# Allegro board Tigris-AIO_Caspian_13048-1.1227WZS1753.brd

Outline 206.6 x 253.5 mm; copper layers: TOP, L2GND, L3, L4, L5GND, BOTTOM. Coordinates in mm from the lower left corner of the outline.
Outline path: 0,252.5 0,1 arc(0.29,0.29) 1,0 134,0 arc(134.58,0.18) 134.94,0.67 arc(135.13,0.91) 135.41,1 171,1 arc(171.71,1.29) 172,2 172,45.91 arc(172.01,46) 172.03,46.09 179.5,65.83 arc(179.68,66.06) 179.97,66.15 203.75,66.15 arc(204.46,66.44) 204.75,67.15 204.75,135.8 arc(205.04,136.51) 205.75,136.8 206.1,136.8 arc(206.45,136.95) 206.6,137.3 206.6,171.8 arc(206.45,172.15) 206.1,172.3 205.75,172.3 arc(205.04,172.59) 204.75,173.3 204.75,173.99 arc(204.67,174.37) 204.46,174.69 188.15,191 arc(188.04,191.17) 188,191.36 188,230 arc(187.71,230.71) 187,231 159.5,231 158,229.5 158,229.25 arc(157.85,228.9) 157.5,228.75 120.5,228.75 arc(120.15,228.9) 120,229.25 120,252.5 arc(119.71,253.21) 119,253.5 1,253.5 arc(0.29,253.21) 0,252.5

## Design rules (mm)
constraint set DEFAULT: min track width 0.127, pair gap 0.102
net group CARDREADER_20: nets CR_AUX_CAP CR_IO_CAP
net group GPU_ODT-MW: nets ODTA0 ODTA1
net group LED_10_6: nets PWR_LED_YELLOW_1 SUS_LED_GREEN_1
net group PWM_20_10: nets 1589_VCC AUD_REGREF
net group SIO_IT8731-4_5-MV-MW: nets SIO_ATXPG SIO_ATXPG_C
net group VRD_10_10-10.5: nets VCC_SENSE VSS_SENSE
net group 5MIL: nets 3.3V_RUN_VGA_1 5VDDCCL 5VDDCDA +19V_AMP_AVCC AUD_DVDD DDPB_CTRL_CLK DDPB_CTRL_DATA DDPC_CTRL_CLK DDPC_CTRL_DATA DDPD_CTRL_CLK DDPD_CTRL_DATA DISP_UTIL_CPU DPLL_PVDD DPLL_VDDC FDI_CSYNC FDI_INT G_H_DDCDA_1 G_H_DDCSCL_1 GND_AUD GPIO_8_ROMSO GPIO_9_ROMSI GPIO_10_ROMSCK GPIO_22_ROMCS# L_BKLTEN L_VDD_EN PCH_JTAG_PWR ROM_CS# ROM_SI_D3 ROM_SLK_D4 ROM_SO_C4 SA0_DIM0 SA0_DIM1 SA1_DIM0 SA1_DIM1 SATA1GP SATA3GP SIO_SPKR SPI_CLK SPI_CLK_1 SPI_CLK_R SPI_CS0_N SPI_CS0_N_R SPI_CS1_N SPI_IO2 SPI_IO2_R SPI_IO3 SPI_IO3_R SPI_MISO SPI_MISO_R SPI_MISO_ROM_1 SPI_MOSI SPI_MOSI_1 SPI_MOSI_R SPI_WP_N_1 SPKR SPKR_1 SPV10 SPV18 SST_HOLDJ_1 SWR_V12 TP_1P5_PCH_PWROK TP_1P5_PCH_PWROK_1 TP_ALL_PWRGD TP_CPU_G38 TP_CPU_H37 TP_CPU_H38 TP_CPU_J38 TP_CPU_K37 TP_CPU_K39 TP_CPU_M38 TP_CPU_N36 TP_CPU_T35 TP_DISP_J12 TP_DISP_K11 TP_GPIO52 TP_GPU_CLKREQ# TP_H_CATERR_N TP_LPC_DRQ0_N TP_NGFF_COEX1 TP_NGFF_COEX2 TP_NGFF_COEX3 TP_NGFF_LED1 TP_NGFF_LED2 TP_NGFF_MLDIR TP_PCH_A2 TP_PCH_A3 TP_PCH_AE30 TP_PCH_AH24 TP_PCH_AJ14 TP_PCH_AK14 TP_PCH_AM34 TP_PCH_AN16 TP_PCH_AP18 TP_PCH_AV13 TP_PCH_B1 TP_PCH_B2 TP_PCH_K16 TP_PCH_K22 TP_PCH_K33 TP_PCH_K34 TP_PCH_L16 TP_PCH_L22 TP_PCH_N12 TP_PCH_P19 TP_PCH_PWM0 TP_PCH_PWM1 TP_PCH_PWM2 TP_PCH_PWM3 TP_PCH_R12 TP_PCH_U10 TP_PCH_U11 TP_PEG_A4 TP_PEG_B3 TP_PEG_C2 TP_PEG_D1 TP_RSVD_AB6 TP_RSVD_AB33 TP_RSVD_AB36 TP_RSVD_AC8 TP_RSVD_AK20 TP_RSVD_AT40 TP_RSVD_AU1 TP_RSVD_AU27 TP_RSVD_AU39 TP_RSVD_AV1 TP_RSVD_AV2 TP_RSVD_AV20 TP_RSVD_AV24 TP_RSVD_AV29 TP_RSVD_AW2 TP_RSVD_AW12 TP_RSVD_AW23 TP_RSVD_AW24 TP_RSVD_AW27 TP_RSVD_AY18 TP_RSVD_C39 TP_RSVD_H12 TP_RSVD_H14 TP_RSVD_H15 TP_RSVD_H16 TP_RSVD_J8 TP_RSVD_J9 TP_RSVD_J10 TP_RSVD_J13 TP_RSVD_J15 TP_RSVD_J16 TP_RSVD_J17 TP_RSVD_J40 TP_RSVD_K8 TP_RSVD_K12 TP_RSVD_K13 TP_RSVD_L10 TP_RSVD_L12 TP_RSVD_M10 TP_RSVD_M11 TP_RSVD_N38 TP_RSVD_P33 TP_RSVD_P37 TP_RSVD_R33 TP_RSVD_R34 TP_RSVD_R36 TP_RSVD_T34 TP_RSVD_U8 TP_RSVD_V7 TP_RSVD_W8 TP_RSVD_Y8 TP_SLP_LAN_N_C TP_TPM_PIN6 TP_TPM_PIN7 V_1P5_DAC_FB V_1P5_DAC_FB_R V_1P05_DSW_INT_C V_1P05_DSW_INT_R V_1P05_ME V_1P05_PECI_VCOM V_1P5_RTC_INT V_1P05_XCK_DCB_FB_R V_3P3_BG V_5_CODEC V_CPU_VCCIO2PCH V_CPU_VCCIO_OUT V_CPU_VCCIO_RIGHT V_VCCIOA_LOAD VCCIO2PCH VCCST VGA_DDC_PU VGA_PCH_DDCSCL VGA_PCH_DDCSDA
net group 5MIL-1: nets H_PROCHOT_N H_PROCHOT_R_N H_VID0 H_VID1 H_VID2 H_VID3 H_VID4 H_VID5 H_VID6 H_VIDALERT_N H_VIDALERT_N_1 H_VIDALERT_N_VR H_VIDSCK H_VIDSCK_VR H_VIDSOUT H_VIDSOUT_VR PWR_VGA_CORE_VID0 PWR_VGA_CORE_VID1 PWR_VGA_CORE_VID2 PWR_VGA_CORE_VID3 PWR_VGA_CORE_VID4 PWR_VGA_CORE_VID5 PWR_VGA_CORE_VID6
net group 6MIL: nets DDRVTT_REF M_CAS_A_N M_MAA_A0 M_MAA_A1 M_MAA_A2 M_MAA_A3 M_MAA_A4 M_MAA_A5 M_MAA_A6 M_MAA_A7 M_MAA_A8 M_MAA_A9 M_MAA_A10 M_MAA_A11 M_MAA_A12 M_MAA_A13 M_MAA_A14 M_MAA_A15 M_RAS_A_N M_SBS_A0 M_SBS_A1 M_SBS_A2 M_WE_A_N TS#_DIMM0_1
net group 7.5MIL: nets M_ODT_A0 M_ODT_A1 M_SCKE_A0 M_SCKE_A1 M_SCS_A_N0 M_SCS_A_N1
net group 7MIL: nets DSWVRMEN FWH_ID0 INIT_3V L_AD0 L_AD0_R L_AD1 L_AD1_R L_AD2 L_AD2_R L_AD3 L_AD3_R L_FRAME_N L_FRAME_N_R L_PWRDWN_N LPC_DRQ1_N P_GNT_N1 P_GNT_N2 P_GNT_N3 P_INTA_N P_INTB_N P_INTC_N P_INTD_N P_PME# PCH_PCIECLKRQ1_N PCH_PCIECLKRQ5_N PCH_PCIECLKRQ6_N PCH_PCIECLKRQ6_N_1 PCH_RI SER_IRQ
net group 8.5MIL: nets M_DATA_A0 M_DATA_A1 M_DATA_A2 M_DATA_A3 M_DATA_A4 M_DATA_A5 M_DATA_A6 M_DATA_A7 M_DATA_A8 M_DATA_A9 M_DATA_A10 M_DATA_A11 M_DATA_A12 M_DATA_A13 M_DATA_A14 M_DATA_A15 M_DATA_A16 M_DATA_A17 M_DATA_A18 M_DATA_A19 M_DATA_A20 M_DATA_A21 M_DATA_A22 M_DATA_A23 M_DATA_A24 M_DATA_A25 M_DATA_A26 M_DATA_A27 M_DATA_A28 M_DATA_A29 M_DATA_A30 M_DATA_A31 M_DATA_A32 M_DATA_A33 M_DATA_A34 M_DATA_A35 M_DATA_A36 M_DATA_A37 M_DATA_A38 M_DATA_A39 M_DATA_A40 M_DATA_A41 M_DATA_A42 M_DATA_A43 M_DATA_A44 M_DATA_A45 M_DATA_A46 M_DATA_A47 M_DATA_A48 M_DATA_A49 M_DATA_A50 M_DATA_A51 M_DATA_A52 M_DATA_A53 M_DATA_A54 M_DATA_A55 M_DATA_A56 M_DATA_A57 M_DATA_A58 M_DATA_A59 M_DATA_A60 M_DATA_A61 M_DATA_A62 M_DATA_A63
net group 8MIL: nets SLP_SUSB SUS3V_FON_N SUS3V_ON_N SUS5V_ON_N SUS_PWR_ACK SUS_WARNB
net group 10MIL: nets BKLT_ADJ CLINK_CLK_LAN CLINK_CLK_LAN_1 CLINK_DATA_LAN CLINK_DATA_LAN_1 CLINK_RST_LAN_N CLINK_RST_LAN_N_1 CPU_FAN_CTRL_SIO CPU_FAN_TACH_SIO DPLVDS_EDIDCLK DPLVDS_EDIDCLK_C DPLVDS_EDIDSDA DPLVDS_EDIDSDA_C DPLVDS_FWCLK DPLVDS_FWCLK_C DPLVDS_FWSDA DPLVDS_FWSDA_C DPLVDS_ISPCLK DPLVDS_ISPDAT DPLVDS_PWMIN DPLVDS_PWMOUT EAPD_DEPOP FAN_CTL3 FAN_TAC3 GPIO_VGA_03_DATA GPIO_VGA_03_DATA_R GPIO_VGA_04_CLK GPIO_VGA_04_CLK_R H_PECI ISP_CLK1 ISP_DAT1 LVDS_BL_ADJ M1_SMB_CLK M1_SMB_DATA PCH_LVDS_BL_ADJ PECI_PCH PECI_READY PECI_SIO_R SIO_LVDS_BL_ADJ SIO_PECI_REQ_N SIO_SMBCLK1 SIO_SMBCLK2 SIO_SMBDAT1 SIO_SMBDAT2 SIO_TACH3 SMB_ALERT_N SMB_CLK_MAIN SMB_CLK_RESUME SMB_DATA_MAIN SMB_DATA_RESUME SMBUS_ISP SMLICLK_PCH SMLIDATA_PCH SMLINK0_CLK SMLINK0_DATA SP_CTS_N SP_DCD_N SP_DSR_N SP_DTR_N SP_RI_N SP_RTS_N SP_RXD_N SP_TXD_N SP_TXD_SIO SST_CTL_R SYS_FAN_TACH3_1 SYS_FAN_TACH3_2 SYSTEM_FAN_PWM1_2 TD_IREF
net group 12MIL: nets DDSP_B_TX_DN_3 DDSP_B_TX_DP_3 VGA_DACREFSET
net group 15MIL: nets A20GATE CK_14M_FLEX CK_14M_PCH CK_14M_SIO CK_14M_TPM CK_33M_PCI0 CK_33M_PCI1 CK_33M_PCI2 CK_33M_PCI3 CK_33M_PCI4 CK_P_33M_LPCP80 CK_P_33M_SIO CK_P_33M_TPM CK_PCH_33M_FB CLKOUTFLEX1 DMICOMP DMIRCOMP FDI_RCOMP HSYNC_3P3V NGFF_CLKREQ0_N NGFF_CLKREQ1_N PCIAUX_GATE PEG_COMP SATARBIAS_PCH SPKR_L+_SNB SPKR_L-_SNB SPKR_OUT_L+ SPKR_OUT_L- SPKR_OUT_R+ SPKR_OUT_R- SPKR_R+_SNB SPKR_R-_SNB SUS_PWR_ACK_R SUS_WARNB_R SUSCLK SUSCLK_1 SUSCLK_NGFF SUSCLK_SIO TPA3131_BSNL TPA3131_BSNR TPA3131_BSPL TPA3131_BSPR VGA_HSYNC_3V VGA_VSYNC_3V VSYNC_3P3V XCLK_RCOMP
net group 20MIL: nets BLUE_CRT GREEN_CRT LAN_XTALI LAN_XTALO PCH_RTCRST_DOWN PCH_RTCX1 PCH_RTCX2 RED_CRT RTCX_L VGA_BLUE VGA_BLUE_C_L VGA_GREEN VGA_GREEN_C_L VGA_RED VGA_RED_C_L XTAL_25M_PCH_IN XTAL_25M_PCH_OUT XTALIN XTALOUT
net group AUDIO-4MW: nets AUD_BEEP_C AUD_BEEP_R AUD_LINK_BCLK AUD_LINK_BCLK_R AUD_LINK_RST_N AUD_LINK_RST_R_N AUD_LINK_SDIN AUD_LINK_SDIN_1 AUD_LINK_SDO AUD_LINK_SDO_1 AUD_LINK_SDO_R AUD_LINK_SDO_R1 AUD_LINK_SYNC AUD_LINK_SYNC_R BUZZER_SPKR_R PCH_AUD_MUTE PCH_AUD_RST_N PCH_AUD_RST_N_1 TPA3113_SD1#
net group AUDIO-5: nets AUD_DMIC_CLK AUD_DMIC_CLK_R AUD_DMIC_DATA AUD_DMIC_DATA_R
net group AUDIO_AMP_15: nets AMP_SPKR_L AMP_SPKR_R PORTC_SPK_L PORTC_SPK_L_1 PORTC_SPK_R PORTC_SPK_R_1 SPKR_IN_L SPKR_IN_R TP3131_GVDD TPA3131_GAIN TPA3131_LINN TPA3131_LINN_1 TPA3131_MUTE TPA3131_PLIMIT TPA3131_RINN TPA3131_RINN_1 TPA3131_SYNC
net group AUDIO_DMIC_MW: nets AUD_DMIC_CLK_R_1
net group AUDIO_HDA-MW: nets AUD_LINK_RST_N_R AUD_LINK_SDO_N SENSE_B SLEEVE_G
net group AUDIO_IO: nets AUD_GP3 HPOL_CON HPOR_CON HPOUT-JD HPOUT-L HPOUT-R LINE2-VREFO LINEOUT-JD LINEOUT-L LINEOUT-R LINEOUT_C-L LINEOUT_C-R LINEOUT_CON-L LINEOUT_CON-R MIC2-L MIC2-L_1 MIC2-R MIC2-R_1 MIC2-VREFO-L MIC2-VREFO-R
net group AUDIO_IO_REF: nets JDREF MIC-CAP VRP
net group AUDIO_POP-MW: nets TPA3131_FAULT#
net group CARDREADER-4MW: nets CR_CLKREQ_N CR_LDOSEL CR_PE_REXT CR_WAKE0_N SD_CD# SD_CLK SD_CLK_C_1 SD_CLK_C_2 SD_CMD SD_CMD_C SD_DAT0 SD_DAT0_C SD_DAT1 SD_DAT1_C SD_DAT2 SD_DAT2_C SD_DAT3 SD_DAT3_C SD_LDO_EN SD_LED SD_WP
net group CPU-4MW: nets CPU_THERMTRIP_N H_PM_SYNC_0 H_PRDY_N H_PREQ_N H_SKTOCC_N H_SKTOCC_R_N H_TCK H_TDI H_TDO H_TMS H_TRST_N HSW_PCUDEBUG_0 HSW_PCUDEBUG_1 HSW_PCUDEBUG_2 HSW_PCUDEBUG_3 HSW_PCUDEBUG_4 HSW_PCUDEBUG_5 HSW_PCUDEBUG_6 HSW_PCUDEBUG_7 HSW_PCUDEBUG_8 HSW_PCUDEBUG_9 HSW_PCUDEBUG_10 HSW_PCUDEBUG_11 HSW_PCUDEBUG_12 HSW_PCUDEBUG_13 HSW_PCUDEBUG_14 HSW_PCUDEBUG_15 HSW_PCUSTB_0_DN HSW_PCUSTB_0_DP HSW_PCUSTB_1_DN HSW_PCUSTB_1_DP HSW_STRAP_13 HSW_XDP_MBP_0 HSW_XDP_MBP_1 PRIVACY_MSR_EN_N PWR_DEBUG PWR_DEBUG_1 PWR_DEBUG_N V_1P5_STBY_INT VCCST_PWRGD XDP_PWR_DEBUG
net group CPU-12: nets TPEV_CFG_RCOMP
net group DDR3_A-10: nets DIMM_CA_CPU_VREF_A DIMM_CA_CPU_VREF_RC DIMM_CA_VREF_A DIMM_CA_VREF_A_L DIMM_DQ_CPU_VREF_A DIMM_DQ_CPU_VREF_A_1 DIMM_DQ_CPU_VREF_B_1 DIMM_DQ_VREF_A DIMM_DQ_VREF_A_L
net group DDR3_B-5.5MW: nets M_DATA_B0 M_DATA_B1 M_DATA_B2 M_DATA_B3 M_DATA_B4 M_DATA_B5 M_DATA_B6 M_DATA_B7 M_DATA_B8 M_DATA_B9 M_DATA_B10 M_DATA_B11 M_DATA_B12 M_DATA_B13 M_DATA_B14 M_DATA_B15 M_DATA_B16 M_DATA_B17 M_DATA_B18 M_DATA_B19 M_DATA_B20 M_DATA_B21 M_DATA_B22 M_DATA_B23 M_DATA_B24 M_DATA_B25 M_DATA_B26 M_DATA_B27 M_DATA_B28 M_DATA_B29 M_DATA_B30 M_DATA_B31 M_DATA_B32 M_DATA_B33 M_DATA_B34 M_DATA_B35 M_DATA_B36 M_DATA_B37 M_DATA_B38 M_DATA_B39 M_DATA_B40 M_DATA_B41 M_DATA_B42 M_DATA_B43 M_DATA_B44 M_DATA_B45 M_DATA_B46 M_DATA_B47 M_DATA_B48 M_DATA_B49 M_DATA_B50 M_DATA_B51 M_DATA_B52 M_DATA_B53 M_DATA_B54 M_DATA_B55 M_DATA_B56 M_DATA_B57 M_DATA_B58 M_DATA_B59 M_DATA_B60 M_DATA_B61 M_DATA_B62 M_DATA_B63
net group DDR3_B-6.5MW: nets M_ODT_B0 M_ODT_B1 M_SCKE_B0 M_SCKE_B1 M_SCS_B_N0 M_SCS_B_N1
net group DDR3_B-8.5MW: nets M_CAS_B_N M_MAA_B0 M_MAA_B1 M_MAA_B2 M_MAA_B3 M_MAA_B4 M_MAA_B5 M_MAA_B6 M_MAA_B7 M_MAA_B8 M_MAA_B9 M_MAA_B10 M_MAA_B11 M_MAA_B12 M_MAA_B13 M_MAA_B14 M_MAA_B15 M_RAS_B_N M_SBS_B0 M_SBS_B1 M_SBS_B2 M_WE_B_N
net group DDR3_B-25: nets DIMM_CA_VREF_B DIMM_CA_VREF_B_L DIMM_DQ_CPU_VREF_B DIMM_DQ_VREF_B DIMM_DQ_VREF_B_L
net group DDR_COMP_12_25-12: nets DDR_RCOMP_0 DDR_RCOMP_1 DDR_RCOMP_2
net group DISPLAY-12: nets FDI_COMP
net group GND: nets VSS_MECH
net group GPIO_4-MW: nets ADAPTOR_PSID ADAPTOR_PSID_R DDSP_B_HPD DDSP_B_HPD_CONN JACK_PSID LVDS_DET_B_R NGFF_BT_DISABLE NGFF_DETECT_PCIE NGFF_DETECT_PCIE_C NGFF_DETECT_USB NGFF_DETECT_USB_C PCH_GP33_PU PCH_GPIO20 PSID_D PSID_D_1 PSID_G SIO_GREEN_GP000 SPKR_DET SPKR_DET_C USB_PWR_CRL1 USB_PWR_CRL1_B1 VGA_DET
net group GPIO_4-MW-4MW: nets 2136_HPD_C BIST_DISABLE BIST_EN_INV BIST_ENABLE BIST_ENABLE_1 BOARD_A BOARD_B BOARD_C DPD_HPD DPLVDS_HPD EAPD_DEPOP_1 GPIO17_THERMAL_INT GPIO19_CTF GPU_THERMAL_INT IGC_EN_N INTRUDER_DET INV_DET* IO_SMI_N LAN_DISABLE_N LPC_PME_N LVDS_DET_A* LVDS_DET_B* MB_SKU_ID0 MB_SKU_ID1 MB_SKU_ID2 ME_CNTL ME_CNTL1 ME_CNTL2 MPCIE_DISABLE_N OSD_BIST_N OSD_DN OSD_DN_R OSD_MENU OSD_MENU_R OSD_UP OSD_UP_R PANEL_SEL1_CABLE_PCH PANEL_SEL2_CABLE_PCH PANEL_SEL3_CABLE_PCH PCH_GP8 PCH_GP27_PU PECI_REQ_N PW_CLEAR PWRCN_DET_N QF2_1 QF2_2 SATA2GP SATA4GP SATA5GP SIO_HDD_LED SIO_HDD_LED_1 SLP_WLAN_N TMIN_SHIFT WEBCAM_DET
net group GPU-4MW: nets CLKTESTA CLKTESTA_C CLKTESTB CLKTESTB_C CTF_TRIP CTFB GPIO19_CTF_R GPU_THERM_SHUTDOWN* JTAG_TCK_VGA JTAG_TDI_VGA JTAG_TDO_VGA JTAG_TMS_VGA JTAG_TRST#_VGA MEM_CALRP0 MLPS_EN# PCIE_CALR_RX PCIE_CALR_TX PS_0 PS_1 PS_2 PS_3 VRAM_ZQ1 VRAM_ZQ2 VRAM_ZQ3 VRAM_ZQ4
net group GPU-20: nets MVREFDA MVREFSA VRAM1_VREFCA VRAM1_VREFDQ VRAM2_VREFCA VRAM2_VREFDQ VRAM3_VREFCA VRAM3_VREFDQ VRAM4_VREFCA VRAM4_VREFDQ
net group GPU_ADDRESS-MW: nets MAA0 MAA1 MAA2 MAA3 MAA4 MAA5 MAA6 MAA7 MAA8 MAA9 MAA10 MAA11 MAA12 MAA13 MAA_BA0 MAA_BA1 MAA_BA2
net group GPU_CTRL-MW: nets CASA0# CASA1# CKEA0 CKEA1 CSA0#_0 CSA1#_0 RASA0# RASA1# WEA0# WEA1#
net group GPU_DATA-MW: nets DQMA0 DQMA1 DQMA2 DQMA3 DQMA4 DQMA5 DQMA6 DQMA7 MDA0 MDA1 MDA2 MDA3 MDA4 MDA5 MDA6 MDA7 MDA8 MDA9 MDA10 MDA11 MDA12 MDA13 MDA14 MDA15 MDA16 MDA17 MDA18 MDA19 MDA20 MDA21 MDA22 MDA23 MDA24 MDA25 MDA26 MDA27 MDA28 MDA29 MDA30 MDA31 MDA32 MDA33 MDA34 MDA35 MDA36 MDA37 MDA38 MDA39 MDA40 MDA41 MDA42 MDA43 MDA44 MDA45 MDA46 MDA47 MDA48 MDA49 MDA50 MDA51 MDA52 MDA53 MDA54 MDA55 MDA56 MDA57 MDA58 MDA59 MDA60 MDA61 MDA62 MDA63
net group GPU_OTHER_4-6-MW: nets GPIO_SVC GPIO_SVD GPIO_SVT GPU_CLKA0_T GPU_CLKA1_T GPU_GPIO16 GPU_SCL GPU_SDA GPU_WAKEB GPU_XO_IN GPU_XO_IN2
net group GPU_VREF: nets GPU_VREFG
net group HDMI-MW: nets DDPC_CTRL_CLK_CONN DDPC_CTRL_DATA_CONN DDSP_C_HPD DDSP_C_HPD_CONN DDSP_D_TX_N0 DDSP_D_TX_N2 VCC5_DDC_HDMI
net group LAN_OTHER-4MW: nets LAN_RSET LANCLK_REQ_N LANCLK_REQ_U_N RTL_ISOLATE_N RTL_ISOLATE_N_1 RTL_ISOLATE_N_2
net group LAN_OTHER-10: nets LAN_P5_CN
net group LED_10_6-10: nets LAN_LEDACT_R# LINK_ACTIVITY_N PB_IN_SW1 PCH_SATA_LED_1 PCH_SATA_LED_N PCH_SATA_LED_R PWR_LED_YELLOW_C SIO_GREEN SIO_YELLOW SPEED_100*_CON SPEED_100_N SPEED_1000*_CON SPEED_1000_N SUS_LED_GREEN_C
net group NGFF_OTHER-MW: nets NGFF_ALERT_N NGFF_PEWAKE0_N NGFF_POWER_CTRL NGFF_POWER_CTRL_1 NGFF_W_DISABLE1_N NGFF_W_DISABLE2_N
net group OTHER_4_5-MW: nets CLKBUF_EN
net group OTHER_4_5-MW-4MW: nets CPU_VSS_T8 KCLK KDAT MCLK MDAT SYS_FAN_TACH1_1 SYS_FAN_TACH1_2 SYSTEM_FAN_PWM1_1 TESTLOW_1 TESTLOW_2 TP_DET
net group PANEL_CONTROL-MW: nets LVDS_PU_4 LVDS_PU_5 LVDS_PU_6 LVDS_PU_24 PANEL_ON_1 PANEL_ON_2 PANEL_ON_3 PANEL_ON_4 PANEL_ON_5 S_PANEL_ON
net group PANEL_CONTROL-MW-4MW: nets BKLT_EN BKLT_EN1 DPLVDS_BL_EN DPLVDS_PANEL_VCC PANEL_SEL1_CABLE PANEL_SEL2_CABLE PANEL_SEL3_CABLE S_LVDS_BL_EN
net group PCIE_PCIECLKRQ-MW: nets PCH_PCIECLKRQ5_N_1
net group POWER_RTC_35_5: nets VBAT1_C
net group POWER_RTC_35_5-35: nets V_3P0_BAT_VREG VBAT1_R VBAT2
net group POWER_SENSE_10_10: nets 12V_PWR_SENSE
net group PWM_10_10: nets 1589_COMP 1589_CP1 1589_FB 1589_FB1 1589_VOS RT8243_ENTRIP1_1 RT8243_ENTRIP1_2 RT8243_ENTRIP2_1 RT8243_ENTRIP2_2
net group PWM_10_10-10: nets 0D95V_VGA_FB 0D95V_VGA_FB_1 0D95V_VGA_FB_2 0D95V_VGA_FB_3 1D05V_EN 1D05V_RF 1D05V_TRIP 1D05V_VFB 1D8V_VGA_EN 1D8V_VGA_FB 1D8V_VGA_POK 1P5_PCH_EN 1P5_PCH_FB 3.3V_ALW_1 3D3V_VGA_S0_EN 62882_COMP_R 62882_FB_VSEN 62882_NTC_R 81102_COMP 81102_COMP_1 81102_COMP_2 81102_CSCCOMP 81102_CSCM_1 81102_CSREF 81102_CSSUM 81102_DIFF 81102_FB 81102_ILIM 81102_IOUT 81102_TSENSE 81102_TSENSE_R 81102_VSN 81102_VSP AUD_LINK_RST_N_2 BIST_DISABLE_1 BIST_EN BOOT1_PHASE1 D_RSMRST_N_1 D_RSMRST_N_2 DDR_EN DDR_PG DDR_RF DDR_TRIP DDR_VFB DRVON EAPD_DEPOP_2 GPUPG_1 GPUPG_2 GPUPG_3 H_PROCHOT_N_R LAN_DISABLE_N_1 LAN_DISABLE_N_2 LED_5VSB LED_V_5P0_A MB_REG_PG_1 MB_REG_PG_2 MB_REG_PG_3 MEM_REG_PG_1 MEM_REG_PG_2 OSD_BIST_N_1 PCH_1D05V_PG_R PHASE1_R PM_DPRSLPVR PRW_VGA_CORE_RBIAS PSI# PWM1_EN PWM2_EN PWM3_EN PWR2_PRSN_1 PWR2_PRSN_2 PWR_VGA_CORE_COMP PWR_VGA_CORE_DPRSLPVR PWR_VGA_CORE_IMON PWR_VGA_CORE_ISEN1 PWR_VGA_CORE_ISEN2 PWR_VGA_CORE_ISUM+ PWR_VGA_CORE_ISUM- PWR_VGA_CORE_NTC PWR_VGA_CORE_ON PWR_VGA_CORE_PGOOD PWR_VGA_CORE_PSI# PWR_VGA_CORE_RTN PWR_VGA_CORE_VSEN PWR_VGA_CORE_VSUM- PWR_VGA_CORE_VW RT8243_3D3VFB RT8243_5VFB RT8243_ENLDO RT8243_ENTRIP1 RT8243_ENTRIP2 RT8243_FB1 RT8243_FB2 RT8243_PGOOD RT8243_TON RT8243SECFB SP_TXD_N_1 SUS_ACK_EN_N SUS_PWR_ACK_5V_DUAL SUS_PWR_ACK_5V_DUAL_L SUS_PWR_ACK_BJT SUS_PWR_ACK_BJT_L TPA3113_SD TSVDD V5_ALW_MON V5_ALW_MON_1 V5_ALW_MON_2 VCC3_3SB_EN_2 VCC5SB_EN_2 VDDC_CT VR_TT# VREG_PCIAUX_PCH VREG_PCIAUX_PCH_1 VSUM_RC VSUM_RR
net group PWM_12_12: nets CSN2_R
net group PWM_12_12-12: nets CSN1 CSN2 CSN3 CSP1 CSP1_R CSP2 CSP2_R CSP3 CSP3_R PWM1 PWM2 PWM3 PWM4
net group PWM_20_10-20: nets 0D95V_VGA_SS 1D05V_V5IIN 81102_RAMP 81102_VCC APL5336_VCNTL CBN CBP CPVEE DDR_V5IIN DPLVDS_PIN16 FP_CBL_DET LDO_3D3V LDO_5V MB_REG_PG MEM_REG_PG PC_SPKR_DET PWM1_VCC PWM2_VCC PWM3_VCC PWR2_PRSNT PWR_VGA_CORE_BOOT1 PWR_VGA_CORE_FB PWR_VGA_CORE_FB2 PWR_VGA_CORE_VCCP PWR_VGA_CORE_VDD PWR_VGA_CORE_VIN PX_EN RT8243_LDO3 RT8243_LDO5 TESTEN TRST_N VIN_DET VREF_1
net group PWM_25_20: nets 1589_BOOT 1589_BT1 1589_LG 1589_LG12 1589_LX1_SNB 1589_UG 1589_UG1 AD+_2
net group PWM_25_20-25: nets 0D95V_VGA_DRV 0D95V_VGA_DRV_1 1D05V_DRVH 1D05V_DRVH_R 1D05V_DRVL 1D05V_SB 1D05V_VBST 1D05V_VBST_R 3D3VSB 5VSB DDR_DRVH DDR_DRVH_R DDR_DRVL DDR_SB DDR_VBST DDR_VBST_R PWM1_BT PWM1_BT_1 PWM1_HG PWM1_HG_1 PWM1_LG PWM1_SNB PWM2_BT PWM2_BT_1 PWM2_HG PWM2_HG_1 PWM2_LG PWM2_SNB PWM3_BT PWM3_BT_1 PWM3_HG PWM3_HG_1 PWM3_LG PWM3_SNB PWR_5V_BOOT1_1 PWR_VGA_CORE_LGATE1A PWR_VGA_CORE_LGATE1B PWR_VGA_CORE_SNB1 PWR_VGA_CORE_UGATE1 PWR_VGA_CORE_UGATE1_R RT8243_BOOT1 RT8243_BOOT2 RT8243_BOOT2_1 RT8243_HG1 RT8243_HG2 RT8243_LGATE1 RT8243_LGATE2 RT8243_UGATE1 RT8243_UGATE2
net group PWM_30_12-30: nets PCH_SATA_LED_2
net group PWM_PHASE: nets +VGA_CORE_PHASE1
net group PWR_EN_4_10-MW: nets 1589_PGOOD
net group PWR_EN_4_10-MW-4MW: nets PCH_1D05V_PG SLP_S3_N_R1 USB_EN USB_EN1 USB_EN2 V_VCC3P3_EN V_VCC3P3_EN_R V_VCC5_EN V_VCC5_EN_R VCTRL_VCC_EN
net group PWR_MONITER: nets INA99B_OUT INA991_IN_N INA991_IN_P LMV393IN+ LMV393IN-
net group PWRGD&RST_4-MW: nets 0D95V_VGA_EN ATX_ON* LAN_DISABLE_V3 NGFF_POWER_CTRL_V2 OCP_6 OCP_7 OCP_7_1 PLTRST_CR PLTRST_TPM_N PSPWRGD SIO_PSON_N_C SIO_PSON_N_C_1 SIO_PSON_N_C_2 SIO_PSON_N_C_3 SIO_PSON_N_C_4 SIO_PSON_N_C_5 SLP_S3_N_4 SLP_S4_N_G
net group PWRGD&RST_4-MW-4MW: nets 1P05_PCH_EN 1P05_PCH_EN_Q48 1P05_PCH_EN_Q48_R 1P05_PCH_EN_R 1P5_PCH_EN_R 1P5_PCH_EN_R_1 AMD_RST# DDR3_DRAMRST_N DDR3_DRAMRST_N_A_1 DDR3_DRAMRST_N_B_1 DDR_SHDN DGPU_PWROK DGPU_PWROK_1D5V DRAM_RST DRAM_RST_R FP_RST_PCH_N H_CPURST_N H_CPURST_SIO_N H_CPURST_SIO_N_1 H_DRAMPWRGD H_DRAMPWRGD_CPU H_PWRGD H_RSTOUT_XDP_N H_THERMTRIP_N KBRST_N LAN_DISABLE_N_3 LAN_DISABLE_N_4 MEM_COMP MEM_RST PCH_DPWROK PCH_MEPWROK_R PCH_RSMRST_N PCH_SLP_M_N PCH_SYSPWROK PCIE_RST# PCIRST1# PCIRST2# PLTRST*_SIO PLTRST_CPU_N PLTRST_CPU_N1 PLTRST_CPU_N2 PLTRST_LAN_N PLTRST_N PLTRST_N_R PLTRST_SL_N PWRBTN_N PWRGD_3V PWRGD_3V_B_1 PWRGD_3V_LL PWRGOOD_GPU PWROK3 PWROK3_1 Q46_PIN2 Q46_PIN3 Q46_PIN6 Q54_B Q54_C RSMRST*_R RSMRST_N RSMRST_SIO_N_1 SIO_PSON_N SLP_S3_N SLP_S3_N_1 SLP_S3_N_2 SLP_S3_N_3 SLP_S3_N_Q46 SLP_S4_N SLP_S4_N_R SLP_S4_SIO SLP_S5_N SUS_STAT_N V_SM_1P5_EN VR_READY WAKE_N XDP_DBRESET_N XDP_PLTRST_N XDP_PWRGD XDP_VR_READY
net group SIO_IT8731-4-4MW: nets SIO_PROCHOT_R_N
net group TCM_5: nets P25_GND TCM_BA0 TCM_BA1 TCM_CLK_RUN TCM_NC5# TCM_NCP
net group TP-MW: nets DCPSUS
net group USB-4MW: nets USB_OC1_R_N USB_OC2_R_N USBOC01* USBOC89* USBOC1011* USBRBIAS_PCH
net group VBAT_RST_4_10-MW-4MW: nets PCH_INTRUDER_L PCH_INTRUDER_N PCH_INTVRMEN PCH_RTCRST_PULLUP PCH_SRTCRSTB_PULLUP
net group XDP-MW-4MW: nets PCH_JTAG_RST_R PCH_JTAG_TCK PCH_JTAG_TDI PCH_JTAG_TDO PCH_JTAG_TMS

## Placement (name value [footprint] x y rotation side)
ATX1  PIN-CONN4B-GP  [G881A04102TEU]  11.06 166.05 270 top
ATX2  PIN-CONN8B-S-GP  [733-71-08TB12]  7.86 140.05 270 top
BT1  BAT-AAA-BAT-034-K01-GP  [AAA-BAT-034-K01]  82.62 215.35 180 top
BTPWR1  JOWLE-CON2-5-GP  [A2541WV0-1EX2PA-6T]  102.62 222.23 270 top
BTRST1  JOWLE-CON2-5-GP  [A2541WV0-1EX2PA-6T]  147.57 111.87 90 top
C1  SCD1U16V2KX-3GP  [C402H22]  104.27 242.55 90 top
C2  SCD1U16V2KX-3GP  [C402H22]  104.27 241.66 90 top
C3  SCD1U16V2KX-3GP  [C402H22]  102.87 240.78 90 top
C4  SCD1U16V2KX-3GP  [C402H22]  102.87 239.89 90 top
C5  SCD1U16V2KX-3GP  [C402H22]  104.65 238.87 90 top
C6  SCD1U16V2KX-3GP  [C402H22]  104.65 237.98 90 top
C7  SC1U10V2KX-1GP  [C402H22]  91 231.72 270 top
C8  SC2D2U10V3KX-1GP  [C603H36]  90.41 228.9 180 top
C9  SCD1U16V2KX-3GP  [C402H22]  91.57 228.52 180 top
C10  SC2K2P50V3KX-GP  [C603]  33.02 227.95 180 top
C11  SC10U25V6KX-4DL-GP  [C1206H71]  176.78 221.73 90 top
C12  SCD1U50V3KX-GP  [C603H36]  166.88 221.09 180 top
C13  SC10U25V6KX-4DL-GP  [C1206H71]  176.78 219.44 90 top
C14  SC10U6D3V3MX-GP  [C603H38]  123.83 217.53 0 top
C15  SC10U6D3V3MX-GP  [C603H38]  125.09 217.53 0 top
C16  SC10U25V6KX-4DL-GP  [C1206H71]  17.84 217.21 270 top
C17  SCD1U16V2KX-3GP  [C402H22]  122.81 217.15 0 top
C18  SC10U25V6KX-4DL-GP  [C1206H71]  176.78 217.15 90 top
C19  SC1U10V2KX-1GP  [C402H22]  143.23 216.37 180 top
C20  SCD1U16V2KX-3GP  [C402H22]  61.75 216.06 0 top
C21  SC1U10V2KX-1GP  [C402H22]  140.54 212.79 90 top
C22  SC10U10V5KX-2GP  [C805H54]  126.75 214.74 180 top
C23  SCD1U10V2KX-5GP  [C402H22]  128.4 214.61 180 top
C24  SCD1U10V2KX-5GP  [C402H22]  129.29 214.61 180 top
C25  SC100P50V2JN-3GP  [C402H22]  62.74 213.34 270 top
C26  SCD1U16V2KX-3GP  [C402H22]  72.52 209.15 270 top
C27  SC22U6D3V5MX-2GP  [C805H58]  129.49 211.95 90 top
C28  SC1U10V2KX-1GP  [C402H22]  143.76 211.82 180 top
C29  SCD1U10V2KX-5GP  [C402H22]  135.59 211.36 270 top
C30  SCD1U10V2KX-5GP  [C402H22]  128.78 210.52 90 top
C31  SC1U10V2KX-1GP  [C402H22]  145.8 208.77 0 top
C32  SC10U10V5KX-2GP  [C805H54]  124.23 208.49 180 top
C33  SCD1U10V2KX-5GP  [C402H22]  125.73 208.26 180 top
C34  SCD1U10V2KX-5GP  [C402H22]  130.18 208.01 180 top
C35  SCD1U10V2KX-5GP  [C402H22]  132.97 208.01 180 top
C36  SCD1U10V2KX-5GP  [C402H22]  131.57 207.5 270 top
C37  SC10U25V6KX-4DL-GP  [C1206H71]  17.91 207.25 90 top
C38  SCD1U16V2KX-3GP  [C402H22]  67.97 206.95 180 top
C39  SCD1U16V2KX-3GP  [C402H22]  79.12 206.1 90 top
C40  SCD1U16V2KX-3GP  [C402H22]  81.08 206.1 270 top
C41  SC1500P50V3KX-GP  [C603]  180.67 205.57 90 top
C42  SC2K2P50V3KX-GP  [C603]  33.4 205.09 0 top
C43  SC10U10V5KX-2GP  [C805H54]  131.19 204.71 270 top
C44  SC1U16V3KX-5GP  [C603H36]  161.93 198.23 90 top
C45  SC10U16V6KX-2GP  [C1206H71]  17.65 198 270 top
C46  SCD1U50V3KX-GP  [C603H36]  180.34 197.09 270 top
C48  SCD1U16V2KX-3GP  [C402H22]  175.77 194.93 270 top
C49  SCD1U16V2KX-3GP  [C402H22]  179.83 188.58 0 top
C50  SC1U16V3KX-2GP  [C603H36]  182.25 185.4 180 top
C51  SC10U16V6KX-2GP  [C1206H71]  17.91 179.82 270 top
C52  SC10U25V6KX-4DL-GP  [C1206H71]  17.91 177.61 270 top
C53  SC22U6D3V5MX-2GP  [C805H58]  76.58 175.31 90 top
C54  SC22U6D3V5MX-2GP  [C805H58]  80.18 175.31 90 top
C55  SC22U6D3V5MX-2GP  [C805H58]  83.76 175.31 270 top
C56  SC10U25V6KX-4DL-GP  [C1206H71]  17.91 175.4 270 top
C57  SC22U6D3V5MX-2GP  [C805H58]  76.58 173.28 90 top
C58  SC22U6D3V5MX-2GP  [C805H58]  80.18 173.28 90 top
C59  SC22U6D3V5MX-2GP  [C805H58]  83.76 173.28 270 top
C60  SC100P50V2JN-3GP  [C402H22]  44.99 171.81 90 top
C61  SC22U6D3V5MX-2GP  [C805H58]  76.58 171.25 90 top
C62  SC22U6D3V5MX-2GP  [C805H58]  80.18 171.25 90 top
C63  SC22U6D3V5MX-2GP  [C805H58]  83.76 171.25 270 top
C64  SC22U6D3V5MX-2GP  [C805H58]  76.58 169.22 90 top
C65  SC22U6D3V5MX-2GP  [C805H58]  80.18 169.22 90 top
C66  SC22U6D3V5MX-2GP  [C805H58]  83.76 169.22 270 top
C67  SCD1U25V3KX-GP  [C603H36]  25.4 167.88 0 top
C68  SC22U6D3V5MX-2GP  [C805H58]  76.58 167.19 90 top
C69  SC22U6D3V5MX-2GP  [C805H58]  80.18 167.19 90 top
C70  SC22U6D3V5MX-2GP  [C805H58]  83.76 167.19 270 top
C71  SC2K2P50V3KX-GP  [C603]  33.4 165.08 180 top
C72  SC22U6D3V5MX-2GP  [C805H58]  76.58 165.15 90 top
C73  SC22U6D3V5MX-2GP  [C805H58]  80.18 165.15 90 top
C74  SC22U6D3V5MX-2GP  [C805H58]  83.76 165.15 270 top
C75  SC1U16V3KX-5GP  [C603H36]  20.19 163.94 180 top
C76  SC22U6D3V5MX-2GP  [C805H58]  76.58 163.12 90 top
C77  SC22U6D3V5MX-2GP  [C805H58]  80.18 163.12 90 top
C78  SC22U6D3V5MX-2GP  [C805H58]  83.76 163.12 270 top
C79  SCD1U16V2KX-3GP  [C402H22]  144.91 162.8 180 top
C81  SC22U6D3V5MX-2GP  [C805H58]  76.58 161.09 90 top
C82  SC22U6D3V5MX-2GP  [C805H58]  80.18 161.09 90 top
C83  SC22U6D3V5MX-2GP  [C805H58]  83.76 161.09 270 top
C84  SCD1U50V3KX-GP  [C603H36]  19.05 148.95 90 bottom
C85  SCD1U25V3KX-GP  [C603H36]  28.45 133.08 0 top
C86  SCD1U25V3KX-GP  [C603H36]  27.18 133.08 0 top
C88  SCD1U16V2KX-3GP  [C402H22]  181.56 159.42 0 top
C89  SC22U6D3V5MX-2GP  [C805H58]  76.58 159.06 90 top
C90  SC22U6D3V5MX-2GP  [C805H58]  80.18 159.06 90 top
C91  SC22U6D3V5MX-2GP  [C805H58]  83.76 159.06 270 top
C92  SC4D7U6D3V3KX-GP  [C603H36]  180.43 158.8 180 top
C93  SCD1U16V2KX-3GP  [C402H22]  182.78 158.98 0 top
C94  SCD1U16V2KX-3GP  [C402H22]  179.2 158.53 0 top
C95  SC4D7U6D3V3KX-GP  [C603H36]  144.53 158.35 0 top
C97  SC4D7U6D3V3KX-GP  [C603H36]  178.29 156.97 270 top
C100  SCD1U16V2KX-3GP  [C402H22]  178.31 155.81 90 top
C101  SCD1U16V2KX-3GP  [C402H22]  180.09 154.29 90 top
C102  SC4D7U6D3V3KX-GP  [C603H36]  180.09 153.15 270 top
C103  SCD1U16V2KX-3GP  [C402H22]  144.27 153.02 0 top
C104  SCD1U16V2KX-3GP  [C402H22]  145.29 153.02 180 top
C105  SCD1U16V2KX-3GP  [C402H22]  183.13 151.88 0 top
C106  SC4D7U6D3V3KX-GP  [C603H36]  182.07 151.49 180 top
C108  SC4D7U6D3V3KX-GP  [C603H36]  179.83 150.73 270 top
C109  SC4D7U6D3V3KX-GP  [C603H36]  145.29 150.22 0 top
C110  SCD1U16V2KX-3GP  [C402H22]  175.23 148.09 180 top
C113  SCD1U25V3KX-GP  [C603H36]  29.44 154.59 270 top
C114  SC100P50V2JN-3GP  [C402H22]  142.49 137.7 90 top
C115  SCD1U16V2KX-3GP  [C402H22]  15.52 147.3 90 top
C116  SCD1U16V2KX-3GP  [C402H22]  15.47 145.91 90 top
C117  SC10U10V5KX-2GP  [C805H54]  185.67 131.94 0 top
C118  SCD1U16V2KX-3GP  [C402H22]  189.1 131.68 180 top
C119  SCD1U16V2KX-3GP  [C402H22]  179.2 124.95 180 top
C120  SCD1U16V2KX-3GP  [C402H22]  180.09 124.95 180 top
C121  SC10U25V5KX-GP  [C805H56]  14.99 125.84 90 top
C122  SCD1U25V3KX-GP  [C603H36]  14.61 124.19 270 top
C123  SCD1U16V2KX-3GP  [C402H22]  14.2 118.14 270 top
C124  SCD1U16V2KX-3GP  [C402H22]  14.22 116.95 270 top
C125  SCD1U16V2KX-3GP  [C402H22]  188.65 110.6 180 top
C126  SC10U10V5KX-2GP  [C805H54]  187.22 110.37 180 top
C127  SC1U10V2KX-1GP  [C402H22]  144.65 109.97 90 top
C128  SC1500P50V3KX-GP  [C603]  176.02 108.7 90 top
C129  SC1U25V3KX-1-GP  [C603H36]  12.32 106.28 180 top
C130  SC1U16V3KX-5GP  [C603H36]  159 105.77 0 top
C131  SC10U6D3V3MX-GP  [C603H38]  45.46 105.64 270 top
C132  SCD1U10V2KX-5GP  [C402H22]  45.59 104.49 270 top
C133  SCD22U10V2KX-1GP  [C402H22]  81.53 107.81 0 top
C134  SCD22U10V2KX-1GP  [C402H22]  82.42 107.81 0 top
C135  SCD22U10V2KX-1GP  [C402H22]  84.45 107.8 0 top
C136  SCD22U10V2KX-1GP  [C402H22]  85.34 107.8 0 top
C137  SCD22U10V2KX-1GP  [C402H22]  86.99 107.8 0 top
C138  SCD22U10V2KX-1GP  [C402H22]  87.88 107.8 0 top
C139  SCD22U10V2KX-1GP  [C402H22]  89.53 107.8 0 top
C140  SCD22U10V2KX-1GP  [C402H22]  90.42 107.8 0 top
C141  SCD1U50V3KX-GP  [C603H36]  165.33 103.54 180 top
C142  SCD1U10V2KX-5GP  [C402H22]  45.59 103.48 270 top
C143  SCD1U16V2KX-3GP  [C402H22]  183.92 103.34 270 top
C144  SCD1U16V2KX-3GP  [C402H22]  183.92 102.45 270 top
C145  SCD1U10V2KX-5GP  [C402H22]  44.19 101.95 180 top
C146  SCD22U10V2KX-1GP  [C402H22]  80.01 105.65 0 top
C147  SCD22U10V2KX-1GP  [C402H22]  80.9 105.65 0 top
C148  SCD22U10V2KX-1GP  [C402H22]  83.06 105.64 0 top
C149  SCD22U10V2KX-1GP  [C402H22]  83.94 105.64 0 top
C150  SCD22U10V2KX-1GP  [C402H22]  85.72 105.64 0 top
C151  SCD22U10V2KX-1GP  [C402H22]  86.61 105.64 0 top
C152  SCD22U10V2KX-1GP  [C402H22]  88.26 105.64 0 top
C153  SCD22U10V2KX-1GP  [C402H22]  89.15 105.64 0 top
C154  SCD1U16V2KX-3GP  [C402H22]  152.93 101.41 180 top
C155  SC10U25V6KX-4DL-GP  [C1206H71]  178.89 101.3 0 top
C156  SC10U25V6KX-4DL-GP  [C1206H71]  181.1 101.3 0 top
C157  SC1U16V3KX-5GP  [C603H36]  165.28 100.75 0 top
C158  SCD01U16V2KX-3GP  [C402H22]  44.45 99.93 180 top
C159  SCD1U50V3KX-GP  [C603H36]  182.83 100.42 0 top
C160  SC1U10V2KX-1GP  [C402H22]  129.67 99.55 90 top
C161  SC220P50V2KX-3DLGP  [C402H22]  176.66 96.68 180 top
C162  SC22P50V2JN-4GP  [C402H22]  183.13 96.38 0 top
C163  SCD1U10V2KX-5GP  [C402H22]  45.21 96.24 0 top
C164  SC10U6D3V3MX-GP  [C603H38]  180.85 96.12 90 top
C165  SC10U6D3V3MX-GP  [C603H38]  177.7 95.92 180 top
C166  SCD1U25V2KX-GP  [C402H22]  184.91 95.36 0 top
C167  SC100P50V2JN-3GP  [C402H22]  174.24 94.52 180 top
C168  SCD1U16V2KX-3GP  [C402H22]  180.47 94.98 90 top
C169  SC10U6D3V3MX-GP  [C603H38]  11.18 94.09 0 top
C170  SC100P50V2JN-3GP  [C402H22]  189.87 94.07 180 top
C172  SC1U10V2KX-1GP  [C402H22]  129.67 92.06 180 top
C173  SCD1U16V2KX-3GP  [C402H22]  133.99 91.98 180 top
C174  SC47P50V2JN-3GP  [C402H22]  117.06 92.02 180 top
C175  SC4D7U6D3V3KX-GP  [C603H36]  186.79 91.8 90 top
C176  SC4D7U6D3V3KX-GP  [C603H36]  189.43 90.41 90 top
C177  SC1U25V3KX-1-GP  [C603H36]  12.19 91.3 270 top
C178  SC1U10V2KX-1GP  [C402H22]  6.03 90.53 270 top
C179  SC2D2U10V3KX-1GP  [C603H36]  186.18 90.36 90 top
C180  SC10U10V5KX-2GP  [C805H54]  11.81 89.52 270 top
C182  SC10U10V5KX-2GP  [C805H54]  6.05 89.14 270 top
C183  SC1U10V2KX-1GP  [C402H22]  153.44 89.82 90 top
C184  SC10U10V5KX-2GP  [C805H54]  187.15 88.76 90 top
C185  SCD1U50V3KX-GP  [C603H36]  37.11 88.53 90 top
C186  SCD1U10V2KX-5GP  [C402H22]  45.72 87.6 270 top
C187  SCD1U16V2KX-3GP  [C402H22]  185.34 87.11 270 top
C188  SC1U10V2KX-1GP  [C402H22]  147.45 92.34 180 top
C189  SC1U10V2KX-1GP  [C402H22]  153.82 96.15 270 top
C190  SC10U25V6KX-4DL-GP  [C1206H71]  37.24 86.8 90 top
C191  SC15P50V3JN-GP  [C603H36]  154.2 86.78 0 top
C192  SCD1U10V2KX-5GP  [C402H22]  45.72 86.71 270 top
C193  SC10U10V5KX-2GP  [C805H54]  187.25 85.56 90 top
C194  SCD1U16V2KX-3GP  [C402H22]  184.56 85.63 0 top
C195  SC1U10V2KX-1GP  [C402H22]  172.26 85.76 270 top
C196  SC1U10V3KX-4GP-U  [C603H36]  173.96 84.59 270 top
C197  SC10U25V6KX-4DL-GP  [C1206H71]  37.24 84.59 90 top
C198  SCD1U16V2KX-3GP  [C402H22]  149.6 84.47 90 top
C199  SCD1U10V2KX-5GP  [C402H22]  44.99 84.14 180 top
C200  SCD68U16V3KX-GP-U  [C603H36]  95.89 88.5 90 top
C201  SC10U10V5KX-2GP  [C805H54]  185.8 82.53 0 top
C202  SC10U10V5KX-2GP  [C805H54]  187.96 82.53 0 top
C204  SC100P50V2JN-3GP  [C402H22]  180.59 81.9 0 top
C205  SC12P50V3JN-GP  [C603H36]  154.69 88.73 90 top
C206  SC100P50V2JN-3GP  [C402H22]  175.51 80.93 0 top
C207  SCD01U16V2KX-3GP  [C402H22]  43.56 80.75 270 top
C210  SC100P50V2JN-3GP  [C402H22]  179.07 80.12 90 top
C211  SCD1U10V2KX-5GP  [C402H22]  45.59 78.59 270 top
C212  SCD1U50V3KX-GP  [C603H36]  37.29 77.94 270 top
C213  SC10U25V6KX-4DL-GP  [C1206H71]  26.57 77.63 0 top
C214  SCD1U10V2KX-5GP  [C402H22]  45.59 77.7 270 top
C215  SC1U10V2KX-1GP  [C402H22]  150.75 75.17 90 top
C216  SCD1U10V2KX-5GP  [C402H22]  45.59 76.81 270 top
C218  SCD01U16V2KX-3GP  [C402H22]  16.41 73.59 180 top
C219  SC1U10V2KX-1GP  [C402H22]  193.68 74.3 0 top
C220  SCD01U16V2KX-3GP  [C402H22]  15.49 73.59 180 top
C222  SCD01U16V2KX-3GP  [C402H22]  14.55 71.42 180 top
C223  SC10U6D3V3MX-GP  [C603H38]  46.18 74.03 0 top
C224  SCD01U16V2KX-3GP  [C402H22]  13.67 71.42 180 top
C226  SCD1U16V2KX-3GP  [C402H22]  38.61 71.87 90 top
C227  SCD082U16V2KX-GP  [C402H22]  91.08 89.62 0 bottom
C228  SC1U10V3KX-3GP  [C603H36]  32.26 71.23 180 top
C229  SCD01U16V2KX-3GP  [C402H22]  38.61 70.98 90 top
C232  SCD1U16V2KX-3GP  [C402H22]  120.68 70.73 180 top
C236  SC1KP50V2KX-1GP  [C402H22]  33.91 68.69 90 top
C238  SCD22U16V3KX-2-GP  [C603H36]  34.29 67.55 90 top
C239  SCD1U25V2KX-GP  [C402H22]  55.17 67.46 270 top
C240  SC1U16V3KX-2GP  [C603H36]  151.76 31.23 0 top
C241  SCD1U16V2KX-3GP  [C402H22]  142.49 32.62 0 top
C242  SCD01U16V2KX-3GP  [C402H22]  36.58 66.4 270 top
C243  SCD1U16V2KX-3GP  [C402H22]  118.75 67.8 90 top
C244  SCD1U16V2KX-3GP  [C402H22]  118.75 66.91 90 top
C245  SC100P50V2JN-3GP  [C402H22]  75.69 64.88 0 top
C246  SC10U25V5KX-GP  [C805H56]  26.29 64.63 90 top
C247  SCD1U16V2KX-3GP  [C402H22]  120.65 64.63 270 top
C248  SCD1U16V2KX-3GP  [C402H22]  156.46 63.74 0 top
C249  SCD22U25V3KX-GP  [C603H40]  86.49 62.98 90 top
C250  SC1U10V2KX-1GP  [C402H22]  136.44 59.4 0 top
C251  SCD01U16V2KX-3GP  [C402H22]  16.89 58.4 270 top
C252  SCD01U16V2KX-3GP  [C402H22]  16.89 57.39 270 top
C253  SC2200P50V2KX-2GP  [C402H22]  55.98 56.3 270 top
C254  SCD01U16V2KX-3GP  [C402H22]  16.92 56.02 270 top
C255  SC2200P50V2KX-2GP  [C402H22]  57.4 55.41 270 top
C256  SCD01U16V2KX-3GP  [C402H22]  16.92 55.13 270 top
C257  SCD1U16V2KX-3GP  [C402H22]  133.99 54.69 270 top
C258  SC1U16V3KX-2GP  [C603H36]  149.45 54.8 90 top
C259  SC12P50V2JN-3GP  [C402H24]  117.34 53 270 top
C260  SC12P50V2JN-3GP  [C402H24]  119.38 53 90 top
C261  SC150P50V2JN-3GP  [C402H22]  128.11 52.18 90 top
C262  SC100P50V2JN-3GP  [C402H22]  42.09 52.16 90 top
C263  SCD1U25V3KX-GP  [C603H36]  149.22 46.72 90 top
C264  SC1U16V3KX-5GP  [C603H36]  139.57 50.49 90 top
C265  SC1U16V3KX-5GP  [C603H36]  128.46 48.66 0 top
C266  SC10U25V5KX-GP  [C805H56]  104.23 47.02 270 top
C267  0R3J-0-U-GP  [R603H22]  155.96 43.34 270 top
C268  SC1U16V3KX-2GP  [C603H36]  161.8 42.91 180 top
C269  SC1U16V3KX-2GP  [C603H36]  163.07 42.91 180 top
C270  SC10U16V6KX-2GP  [C1206H71]  131.96 46.81 270 top
C271  SC4D7U6D3V3KX-GP  [C603H36]  31.45 45.75 90 top
C272  SC1U10V2KX-1GP  [C402H22]  65.02 45.32 90 top
C273  SCD1U16V2KX-3GP  [C402H22]  31.14 44.66 90 top
C274  SCD027U50V3KX-DL-GP  [C603H36]  156.62 41.34 0 top
C275  SCD027U50V3KX-DL-GP  [C603H36]  159.13 40.75 0 top
C276  SCD1U16V2KX-3GP  [C402H22]  102.82 44.49 270 top
C277  SCD027U50V3KX-DL-GP  [C603H36]  165.23 40.5 270 top
C278  SC100P50V2JN-3GP  [C402H22]  158.12 41.13 0 top
C279  0R3J-0-U-GP  [R603H22]  167.26 41.26 0 top
C280  SC4D7U6D3V3KX-GP  [C603H36]  31.75 42.78 180 top
C281  SCD1U25V3KX-GP  [C603H36]  32.92 42.78 180 top
C282  SC470P50V3JN-2GP  [C603H36]  25.07 42.78 180 top
C283  SCD1U25V3KX-GP  [C603H36]  154.05 37.45 180 top
C284  SCD1U16V2KX-3GP  [C402H22]  25.86 41 270 top
C285  SCD1U16V2KX-3GP  [C402H22]  35.51 40.98 90 top
C286  SCD1U16V2KX-3GP  [C402H22]  35.51 40.09 90 top
C287  SCD027U50V3KX-DL-GP  [C603H36]  165.23 35.42 270 top
C288  SC12P50V2JN-3GP  [C402H24]  23.11 39.15 180 top
C289  SC1U10V2KX-1GP  [C402H22]  35.76 38.19 90 top
C290  SCD1U16V2KX-3GP  [C402H22]  16.76 37.07 270 top
C291  SCD1U16V2KX-3GP  [C402H22]  103.94 35.85 90 top
C292  SCD1U50V3KX-GP  [C603H36]  109.86 35.67 90 top
C293  SCD1U50V3KX-GP  [C603H36]  106.25 35.7 270 top
C294  SCD22U16V3KX-2-GP  [C603H36]  155.07 30.08 90 top
C295  SCD1U16V2KX-3GP  [C402H22]  35.77 35.1 90 top
C296  SCD22U16V3KX-2-GP  [C603H36]  164.72 30.97 0 top
C297  SCD1U16V2KX-3GP  [C402H22]  16.74 34.81 90 top
C298  SC10U10V5KX-2GP  [C805H54]  112.37 34.65 180 top
C299  SC12P50V2JN-DL-GP  [C402H22]  23.11 34.58 0 top
C300  SCD1U16V2KX-3GP  [C402H22]  35.77 34.18 90 top
C301  SCD22U16V3KX-2-GP  [C603H36]  157.99 30.08 270 top
C302  SCD22U16V3KX-2-GP  [C603H36]  160.91 30.08 90 top
C303  SCD1U16V2KX-3GP  [C402H22]  16.76 33.89 90 top
C304  SC1KP50V2KX-1GP  [C402H22]  116.51 33.31 270 top
C305  SC4D7U6D3V3KX-GP  [C603H36]  32.98 32.95 0 top
C306  SCD1U50V3KX-GP  [C603H36]  132.31 32.72 0 top
C307  SCD1U50V3KX-GP  [C603H36]  133.58 32.65 180 top
C308  SC4D7U6D3V2MX-GP-U  [C402-TO0D2H26]  63.5 32.62 0 top
C309  SC4D7U6D3V3KX-GP  [C603H36]  24.64 32.66 270 top
C310  SCD1U16V2KX-3GP  [C402H22]  44.7 29.83 180 top
C311  SCD1U16V2KX-3GP  [C402H22]  111 30.08 0 top
C312  SCD1U16V2KX-3GP  [C402H22]  16.76 30.11 270 top
C313  SCD01U50V3JX-1GP  [C603]  150.37 20.94 180 top
C314  SCD01U50V3JX-1GP  [C603]  152.53 26.78 90 top
C315  SCD01U50V3JX-1GP  [C603]  152.53 25.38 90 top
C316  SCD01U50V3JX-1GP  [C603]  149.61 30.59 90 top
C317  SC2D2U10V3KX-1GP  [C603H36]  32.13 29.32 90 top
C318  SCD1U10V2KX-4GP  [C402H20]  47.24 28.81 270 top
C319  SC470P50V3JN-2GP  [C603H36]  20.12 29.19 270 top
C320  SCD1U10V2KX-4GP  [C402H20]  35.43 28.56 270 top
C321  SC1KP50V2KX-1GP  [C402H22]  104.67 28.69 90 top
C322  SC470P50V2KX-3GP  [C402H22]  64.26 28.3 180 top
C323  SCD1U10V2KX-4GP  [C402H20]  47.24 27.92 270 top
C324  SCD1U10V2KX-4GP  [C402H20]  35.43 27.67 270 top
C325  SC1000P50V3JN-GP-U  [C603H36]  146.3 26.91 0 top
C326  SCD68U16V3KX-GP-U  [C603H36]  145.03 21.07 0 top
C327  SC1000P50V3JN-GP-U  [C603H36]  146.3 21.07 0 top
C328  SC1000P50V3JN-GP-U  [C603H36]  145.02 23.97 180 top
C329  SCD68U16V3KX-GP-U  [C603H36]  146.3 23.99 180 top
C330  SCD68U16V3KX-GP-U  [C603H36]  145.03 26.91 0 top
C331  SC1000P50V3JN-GP-U  [C603H36]  145.03 29.83 180 top
C332  SCD68U16V3KX-GP-U  [C603H36]  146.3 29.83 180 top
C333  SC10U10V5KX-2GP  [C805H54]  10.92 27.29 180 bottom
C334  SCD1U10V2KX-4GP  [C402H20]  47.93 26.63 270 top
C335  SCD1U10V2KX-4GP  [C402H20]  59.56 28.81 270 top
C336  SCD1U10V2KX-4GP  [C402H20]  35.43 26.4 270 top
C337  SCD1U10V2KX-4GP  [C402H20]  47.92 25.7 270 top
C338  SC470P50V3JN-2GP  [C603H36]  18.49 25.99 0 top
C339  SCD1U10V2KX-4GP  [C402H20]  35.43 25.51 270 top
C340  SCD1U50V3KX-GP  [C603H36]  131.72 25 0 top
C341  SCD1U50V3KX-GP  [C603H36]  132.97 24.98 0 top
C342  SC470P50V2KX-3GP  [C402H22]  60.07 27.42 180 top
C343  SC3D3P50V2CN-GP  [C402H22]  31.42 21.93 180 top
C344  SC3D3P50V2CN-GP  [C402H22]  40.08 21.88 180 top
C345  SC3D3P50V2CN-GP  [C402H22]  36.88 22.18 180 top
C346  SC3D3P50V2CN-GP  [C402H22]  33.5 21.93 180 top
C347  SC3D3P50V2CN-GP  [C402H22]  31.11 20.51 270 top
C348  SC3D3P50V2CN-GP  [C402H22]  37.36 18.6 90 top
C349  SC10P50V2JN-4GP  [C402H22]  33.15 19.41 90 top
C350  SC10P50V2JN-4GP  [C402H22]  39.32 19.59 90 top
C351  SC10P50V2JN-4GP  [C402H22]  35.23 19.44 270 top
C352  SC47P50V2JN-3GP  [C402H22]  34.54 14.87 180 top
C353  SC47P50V2JN-3GP  [C402H22]  34.49 16.85 180 top
C354  SCD1U16V2KX-3GP  [C402H22]  124.51 14.39 0 top
C355  SC100P50V2JN-3GP  [C402H22]  69.34 11.67 0 top
C356  SC100P50V2JN-3GP  [C402H22]  72.52 11.67 0 top
C357  SCD1U16V2KX-3GP  [C402H22]  113.21 10.07 0 top
C358  SC10U10V5KX-2GP  [C805H54]  111.68 9.94 180 top
C359  SCD1U16V2KX-3GP  [C402H22]  88.16 8.59 0 top
C360  SC10U10V5KX-2GP  [C805H54]  137.46 8.54 180 top
C361  SC10U10V5KX-2GP  [C805H54]  86.74 8.44 180 top
C362  SCD1U16V2KX-3GP  [C402H22]  98.45 7.43 180 top
C363  SC10U10V5KX-2GP  [C805H54]  99.9 7.38 180 top
C364  SCD1U16V2KX-3GP  [C402H22]  106.68 246.62 0 top
C365  SCD1U16V2KX-3GP  [C402H22]  20.32 245.96 0 bottom
C366  SCD1U16V2KX-3GP  [C402H22]  12.09 245.5 0 bottom
C367  SCD1U16V2KX-3GP  [C402H22]  54.86 245.22 0 bottom
C368  SCD1U16V2KX-3GP  [C402H22]  110.11 240.39 0 bottom
C369  SCD1U16V2KX-3GP  [C402H22]  23.67 244.48 0 bottom
C370  SCD01U50V2KX-1GP  [C402H22]  21.39 244.46 180 bottom
C371  SC47P50V2JN-3GP  [C402H22]  18.16 244.46 0 bottom
C372  SC2D2U16V5KX-1GP  [C805H58]  14.73 243.95 90 bottom
C373  SCD1U16V2KX-3GP  [C402H22]  111 240.39 0 bottom
C374  SCD1U16V2KX-3GP  [C402H22]  111.12 237.98 0 bottom
C375  SC1KP50V2KX-1GP  [C402H22]  11.58 242.58 90 bottom
C376  SCD1U16V2KX-3GP  [C402H22]  112.01 237.98 0 bottom
C377  SC4700P25V2KX-3-GP  [C402H24]  9.53 240.39 90 bottom
C378  SC470P50V2KX-3GP  [C402H22]  9.93 238.52 0 bottom
C379  SCD1U16V2KX-3GP  [C402H22]  22.89 238.01 270 bottom
C380  SC22P50V2JN-4GP  [C402H22]  11.94 237.6 180 bottom
C381  SCD1U16V2KX-3GP  [C402H22]  23.39 236.61 180 bottom
C382  SC2200P50V2KX-2GP  [C402H22]  9.4 235.82 90 bottom
C383  SC2200P50V2KX-2GP  [C402H22]  16.03 235.59 90 bottom
C384  SCD1U16V2KX-3GP  [C402H22]  24.64 235.57 180 bottom
C385  SCD01U25V2KX-3GP  [C402H22]  11.96 235.47 180 bottom
C386  SC100P50V2JN-3GP  [C402H22]  16 234.68 270 bottom
C387  SCD1U16V2KX-3GP  [C402H22]  21.87 234.07 90 bottom
C388  SCD1U16V2KX-3GP  [C402H22]  19.84 234.07 90 bottom
C389  SC1KP50V2KX-1GP  [C402H22]  24 232.77 270 bottom
C390  SC470P50V2KX-3GP  [C402H22]  10.92 232.39 180 bottom
C391  SC2D2U10V3KX-1GP  [C603H36]  106.3 228.71 0 bottom
C392  SCD1U16V2KX-3GP  [C402H22]  19.33 232.17 180 bottom
C393  SCD1U16V2KX-3GP  [C402H22]  21.34 232.14 180 bottom
C394  SCD1U16V2KX-3GP  [C402H22]  50.09 228.28 180 bottom
C395  SC1U16V3KX-5GP  [C603H36]  14.79 227.63 270 bottom
C396  SCD1U16V2KX-3GP  [C402H22]  174.75 227.06 270 bottom
C397  SC10U10V5KX-2GP  [C805H54]  174.88 225.66 270 bottom
C398  SC10U6D3V3MX-GP  [C603H38]  105.66 246.74 0 top
C399  SC10U6D3V3MX-GP  [C603H38]  105.03 228.71 0 bottom
C400  SCD1U25V3KX-GP  [C603H36]  22.65 224.9 0 bottom
C401  SCD1U16V2KX-3GP  [C402H22]  112.9 218.42 90 bottom
C402  SC4D7U10V5KX-4GP  [C805H56]  112.83 216.14 0 bottom
C403  SC1U16V3KX-5GP  [C603H36]  14.79 205.27 270 bottom
C404  SCD1U16V2KX-3GP  [C402H22]  133.35 203.44 0 bottom
C405  SCD1U16V2KX-3GP  [C402H22]  132.46 203.44 0 bottom
C406  SCD1U16V2KX-3GP  [C402H22]  128.65 201.3 270 bottom
C407  SCD1U16V2KX-3GP  [C402H22]  128.65 202.19 270 bottom
C408  SCD1U16V2KX-3GP  [C402H22]  127.64 204.07 270 bottom
C409  SCD1U16V2KX-3GP  [C402H22]  127.64 204.96 270 bottom
C410  SCD1U25V3KX-GP  [C603H36]  22.54 202.35 0 bottom
C411  SC4D7U6D3V3KX-GP  [C603H36]  65.66 201.79 0 bottom
C412  SCD1U10V2KX-5GP  [C402H22]  87.23 201.59 0 bottom
C413  SCD022U16V2KX-3GP  [C402H22]  84.05 201.58 0 bottom
C414  SCD1U16V2KX-3GP  [C402H22]  128.68 199.35 270 bottom
C415  SCD1U16V2KX-3GP  [C402H22]  128.68 198.46 270 bottom
C416  SC1U16V3KX-5GP  [C603H36]  184.28 194.42 0 bottom
C417  SCD022U16V2KX-3GP  [C402H22]  165.1 189.72 270 bottom
C418  SCD1U16V2KX-3GP  [C402H22]  157.48 188.32 180 bottom
C419  SCD1U16V2KX-3GP  [C402H22]  164.34 187.69 270 bottom
C420  SCD022U16V2KX-3GP  [C402H22]  159.51 187.31 180 bottom
C421  SC10U25V5KX-GP  [C805H56]  13.72 185.78 270 bottom
C422  SCD1U10V2KX-5GP  [C402H22]  173.48 181.21 270 bottom
C423  SCD1U10V2KX-5GP  [C402H22]  158.75 180.96 270 bottom
C424  SC22U6D3V5MX-2GP  [C805H58]  80.18 173.27 270 bottom
C425  SC22U6D3V5MX-2GP  [C805H58]  80.18 171.25 270 bottom
C426  SC22U6D3V5MX-2GP  [C805H58]  80.17 169.21 270 bottom
C427  SC22U6D3V5MX-2GP  [C805H58]  80.17 167.18 270 bottom
C428  SCD1U16V2KX-3GP  [C402H22]  174.24 164.58 270 bottom
C429  SC4D7U6D3V3KX-GP  [C603H36]  178.69 163.81 0 bottom
C430  SCD1U16V2KX-3GP  [C402H22]  163.83 163.81 180 bottom
C431  SCD1U16V2KX-3GP  [C402H22]  148.21 162.67 180 bottom
C432  SC1U10V2KX-1GP  [C402H22]  180.82 163.31 0 bottom
C433  SC4D7U6D3V3KX-GP  [C603H36]  157.63 162.01 180 bottom
C434  SCD1U16V2KX-3GP  [C402H22]  178.99 161.91 270 bottom
C435  SCD1U16V2KX-3GP  [C402H22]  173.74 161.91 90 bottom
C436  SCD1U16V2KX-3GP  [C402H22]  163.83 161.78 180 bottom
C437  SCD1U16V2KX-3GP  [C402H22]  178.99 160.89 270 bottom
C438  SC1U10V2KX-1GP  [C402H22]  186.18 160.77 270 bottom
C439  SC4D7U6D3V3KX-GP  [C603H36]  173.35 160.77 270 bottom
C440  SC4D7U6D3V3KX-GP  [C603H36]  81.31 160.18 0 bottom
C441  SC4D7U6D3V3KX-GP  [C603H36]  186.58 159.69 90 bottom
C442  SCD1U16V2KX-3GP  [C402H22]  157.61 159.5 0 bottom
C443  SC4D7U6D3V3KX-GP  [C603H36]  163.83 159.37 0 bottom
C444  SCD1U16V2KX-3GP  [C402H22]  174.12 158.73 90 bottom
C445  SCD1U16V2KX-3GP  [C402H22]  186.94 158.61 270 bottom
C446  SCD1U16V2KX-3GP  [C402H22]  186.94 157.72 270 bottom
C447  SCD1U16V2KX-3GP  [C402H22]  174.12 157.72 90 bottom
C448  SCD1U16V2KX-3GP  [C402H22]  163.58 156.45 180 bottom
C449  SC4D7U6D3V3KX-GP  [C603H36]  147.96 156.32 180 bottom
C450  SCD1U16V2KX-3GP  [C402H22]  157.61 156.19 180 bottom
C451  SC1U25V3KX-1-GP  [C603H36]  17.78 145.37 90 bottom
C452  SCD1U16V2KX-3GP  [C402H22]  72.77 155.25 270 bottom
C453  SCD1U16V2KX-3GP  [C402H22]  163.58 154.42 0 bottom
C454  SC4D7U6D3V3KX-GP  [C603H36]  157.61 153.78 0 bottom
C455  SC4D7U6D3V3KX-GP  [C603H36]  147.96 152.89 180 bottom
C456  SCD1U16V2KX-3GP  [C402H22]  178.44 152.51 90 bottom
C457  SCD1U16V2KX-3GP  [C402H22]  163.58 152.38 0 bottom
C458  SCD1U16V2KX-3GP  [C402H22]  178.44 151.49 90 bottom
C459  SC4D7U6D3V3KX-GP  [C603H36]  174.37 151.11 270 bottom
C460  SC4D7U6D3V3KX-GP  [C603H36]  178.82 150.35 90 bottom
C461  SC5P50V2CN-2GP  [C402H22]  183.13 150.22 90 bottom
C462  SCD01U50V2KX-1GP  [C402H22]  16 131.17 180 bottom
C463  SC4D7U6D3V3KX-GP  [C603H36]  174.37 149.84 270 bottom
C464  SC4D7U6D3V3KX-GP  [C603H36]  158.01 149.06 180 bottom
C465  SC4D7U6D3V3KX-GP  [C603H36]  147.96 148.95 0 bottom
C466  SCD1U50V3KX-GP  [C603H36]  17.02 130.92 180 bottom
C467  SCD1U16V2KX-3GP  [C402H22]  156.97 148.7 180 bottom
C468  SCD1U16V2KX-3GP  [C402H22]  157.61 147.18 90 bottom
C469  SCD1U16V2KX-3GP  [C402H22]  163.8 126.48 90 bottom
C470  SCD1U16V2KX-3GP  [C402H22]  163.8 125.59 90 bottom
C471  SCD1U16V2KX-3GP  [C402H22]  149 125.36 270 bottom
C472  SCD1U16V2KX-3GP  [C402H22]  152.17 125.23 270 bottom
C473  SC4D7U6D3V3KX-GP  [C603H36]  172.09 125.08 0 bottom
C474  SCD1U16V2KX-3GP  [C402H22]  152.15 124.27 270 bottom
C475  SC4D7U6D3V3KX-GP  [C603H36]  157.12 124.09 270 bottom
C476  SCD1U16V2KX-3GP  [C402H22]  163.83 123.55 90 bottom
C477  SC1U16V3KX-5GP  [C603H36]  135.89 118.47 270 bottom
C478  SC10U16V6KX-2GP  [C1206H71]  135.59 116.67 270 bottom
C479  SC10U25V5KX-GP  [C805H56]  16.89 117.71 0 bottom
C480  SC1KP50V2KX-1GP  [C402H22]  184.99 115.5 180 bottom
C481  SCD1U16V2KX-3GP  [C402H22]  136.42 112.46 270 bottom
C482  SC1U16V3KX-5GP  [C603H36]  129.16 108.82 270 bottom
C483  SC10U16V6KX-2GP  [C1206H71]  136.25 108.24 180 bottom
C484  SC1U16V3KX-5GP  [C603H36]  138.02 108.11 180 bottom
C486  SCD1U10V2KX-5GP  [C402H22]  45.59 105.13 90 bottom
C488  SC10U10V5KX-2GP  [C805H54]  143.12 104.16 90 bottom
C489  SCD1U10V2KX-5GP  [C402H22]  45.59 104.11 90 bottom
C500  SCD1U10V2KX-5GP  [C402H22]  45.59 102.35 90 bottom
C501  SCD1U16V2KX-3GP  [C402H22]  147.52 101.75 180 bottom
C502  SCD1U16V2KX-3GP  [C402H22]  146.63 101.75 180 bottom
C503  SC1U10V2KX-1GP  [C402H22]  145.74 101.75 180 bottom
C504  SC1U10V2KX-1GP  [C402H22]  144.85 101.75 180 bottom
C505  SC1U10V2KX-1GP  [C402H22]  143.96 101.75 180 bottom
C514  SCD1U10V2KX-5GP  [C402H22]  45.59 101.33 90 bottom
C515  SC10U10V5KX-2GP  [C805H54]  152.92 100.83 180 bottom
C516  SCD1U10V2KX-5GP  [C402H22]  45.59 100.3 90 bottom
C525  SC10U10V5KX-2GP  [C805H54]  186.94 84.18 0 bottom
C529  SCD1U10V2KX-5GP  [C402H22]  44.19 96.24 180 bottom
C533  SC100P50V2JN-3GP  [C402H22]  183.18 95.51 0 bottom
C539  SCD1U16V2KX-3GP  [C402H22]  147.7 93.84 180 bottom
C540  SCD1U10V2KX-5GP  [C402H22]  45.84 93.7 90 bottom
C544  SCD1U16V2KX-3GP  [C402H22]  175.9 87.23 0 bottom
C545  SC100P50V2JN-3GP  [C402H22]  150.86 91.92 0 bottom
C548  SCD1U50V3KX-GP  [C603H36]  134.47 91.55 0 bottom
C550  SCD1U16V2KX-3GP  [C402H22]  176.96 91.6 90 bottom
C551  SC100P50V2JN-3GP  [C402H22]  145.54 91.3 0 bottom
C552  SC100P50V2JN-3GP  [C402H22]  144.65 91.3 0 bottom
C554  SCD1U10V2KX-5GP  [C402H22]  58.67 90.66 90 bottom
C557  SCD1U10V2KX-5GP  [C402H22]  45.85 93.71 270 top
C558  SCD1U10V2KX-5GP  [C402H22]  90.6 85.02 180 bottom
C559  SCD1U10V2KX-5GP  [C402H22]  62.23 91.67 270 bottom
C560  SC10U6D3V3MX-GP  [C603H38]  177.32 90.56 90 bottom
C562  SC10U6D3V3MX-GP  [C603H38]  177.8 85.68 270 bottom
C565  SCD68U16V3KX-GP-U  [C603H36]  98.17 90.92 0 top
C570  SC10U6D3V3MX-GP  [C603H38]  175.01 84.69 90 bottom
C572  SCD1U16V2KX-3GP  [C402H22]  176.78 87.23 180 bottom
C578  SC100P50V2JN-3GP  [C402H22]  148.08 86.04 180 bottom
C579  SC1U10V2KX-1GP  [C402H22]  125.48 85.58 0 bottom
C581  SCD1U16V2KX-3GP  [C402H22]  146.22 85.49 90 bottom
C583  SCD1U10V2KX-5GP  [C402H22]  59.22 84.96 0 bottom
C584  SCD1U16V2KX-3GP  [C402H22]  172.85 81.14 90 bottom
C588  SCD1U10V2KX-5GP  [C402H22]  44.96 84.17 0 bottom
C591  SC1U10V2KX-1GP  [C402H22]  147.96 84.06 270 bottom
C593  SCD082U16V2KX-GP  [C402H22]  91.08 91.53 180 bottom
C598  SCD1U16V2KX-3GP  [C402H22]  126.11 82.66 180 bottom
C599  SCD1U16V2KX-3GP  [C402H22]  127.07 82.64 180 bottom
C600  SCD1U16V2KX-3GP  [C402H22]  151.76 82.03 270 bottom
C601  SC1500P50V3KX-GP  [C603]  29.87 81.95 180 bottom
C602  SCD1U10V2KX-5GP  [C402H22]  45.59 81.76 90 bottom
C606  SCD1U16V2KX-3GP  [C402H22]  149.83 80.13 90 bottom
C608  SCD1U10V2KX-5GP  [C402H22]  43.94 79.09 180 bottom
C609  SC10U6D3V3MX-GP  [C603H38]  136.14 78.63 270 bottom
C612  SCD1U10V2KX-5GP  [C402H22]  45.59 77.57 90 bottom
C613  SC1U10V2KX-1GP  [C402H22]  133.35 77.49 90 bottom
C616  SCD1U10V2KX-5GP  [C402H22]  45.59 76.55 90 bottom
C619  SC1U10V2KX-1GP  [C402H22]  135.53 76.26 180 bottom
C623  SCD1U10V2KX-5GP  [C402H22]  45.59 75.93 270 top
C625  SC1U10V2KX-1GP  [C402H22]  133.55 75.15 270 bottom
C627  SCD1U10V2KX-5GP  [C402H22]  45.59 74.52 90 bottom
C628  SC1U10V2KX-1GP  [C402H22]  136.09 74.29 90 bottom
C631  SC1U10V2KX-1GP  [C402H22]  138.3 73.81 180 bottom
C632  SC1U10V2KX-1GP  [C402H22]  134.03 73.73 180 bottom
C633  SCD1U16V2KX-3GP  [C402H22]  139.87 72.93 180 bottom
C634  SCD1U16V2KX-3GP  [C402H22]  115.06 227.44 180 bottom
C635  SCD1U16V2KX-3GP  [C402H22]  115.95 227.44 180 bottom
C636  SC1U10V2KX-1GP  [C402H22]  136.9 72.71 90 bottom
C638  SC1U10V2KX-1GP  [C402H22]  138.3 71.88 180 bottom
C639  SCD1U16V2KX-3GP  [C402H22]  134.03 71.8 0 bottom
C640  SCD1U16V2KX-3GP  [C402H22]  132.38 70.12 90 bottom
C641  SCD1U16V2KX-3GP  [C402H22]  107.95 218.8 0 top
C642  SCD1U16V2KX-3GP  [C402H22]  107.06 218.8 0 top
C643  SCD1U16V2KX-3GP  [C402H22]  124.83 65.24 180 bottom
C644  SCD1U16V2KX-3GP  [C402H22]  125.75 65.24 180 bottom
C645  SCD1U16V2KX-3GP  [C402H22]  129.03 65.93 0 bottom
C646  SCD1U16V2KX-3GP  [C402H22]  137.46 65.7 0 bottom
C647  SC1U10V2KX-1GP  [C402H22]  145.54 64.91 180 bottom
C648  SCD1U16V2KX-3GP  [C402H22]  144.63 64.91 180 bottom
C649  SCD1U16V2KX-3GP  [C402H22]  146.96 64.86 90 bottom
C650  SC1U10V2KX-1GP  [C402H22]  138.48 64.53 0 bottom
C651  SC1U10V2KX-1GP  [C402H22]  136.32 64.1 0 bottom
C652  SC1U10V2KX-1GP  [C402H22]  146.96 63.98 90 bottom
C653  SC1U10V2KX-1GP  [C402H22]  146.96 63.09 90 bottom
C654  SCD1U16V2KX-3GP  [C402H22]  135.59 62.11 0 bottom
C655  SCD1U16V2KX-3GP  [C402H22]  145.59 39.05 270 bottom
C656  SCD1U16V2KX-3GP  [C402H22]  147.19 44.18 180 bottom
C657  SCD1U16V2KX-3GP  [C402H22]  145.03 44.18 180 bottom
C658  SCD1U16V2KX-3GP  [C402H22]  139.11 61.03 270 bottom
C659  SC1U10V2KX-1GP  [C402H22]  137.46 61.03 180 bottom
C660  SC10U10V5KX-2GP  [C805H54]  156.97 61.32 0 bottom
C661  SCD1U16V2KX-3GP  [C402H22]  158.5 60.56 180 bottom
C662  SC1U10V2KX-1GP  [C402H22]  139.11 59.1 90 bottom
C663  SC10U10V5KX-2GP  [C805H54]  141.07 58.62 0 bottom
C664  SC1U10V2KX-1GP  [C402H22]  145.08 57.18 180 bottom
C665  SC10U10V5KX-2GP  [C805H54]  137.54 54.76 0 bottom
C666  SC10U6D3V3MX-GP  [C603H38]  142.75 44.56 0 bottom
C667  SC10U16V6KX-2GP  [C1206H71]  129.32 52.06 270 bottom
C668  SCD1U16V2KX-3GP  [C402H22]  55.09 51.88 0 bottom
C669  SCD1U16V2KX-3GP  [C402H22]  50.95 51.72 0 bottom
C670  SCD1U16V2KX-3GP  [C402H22]  48.92 51.72 0 bottom
C671  SCD1U16V2KX-3GP  [C402H22]  46.08 51.24 90 bottom
